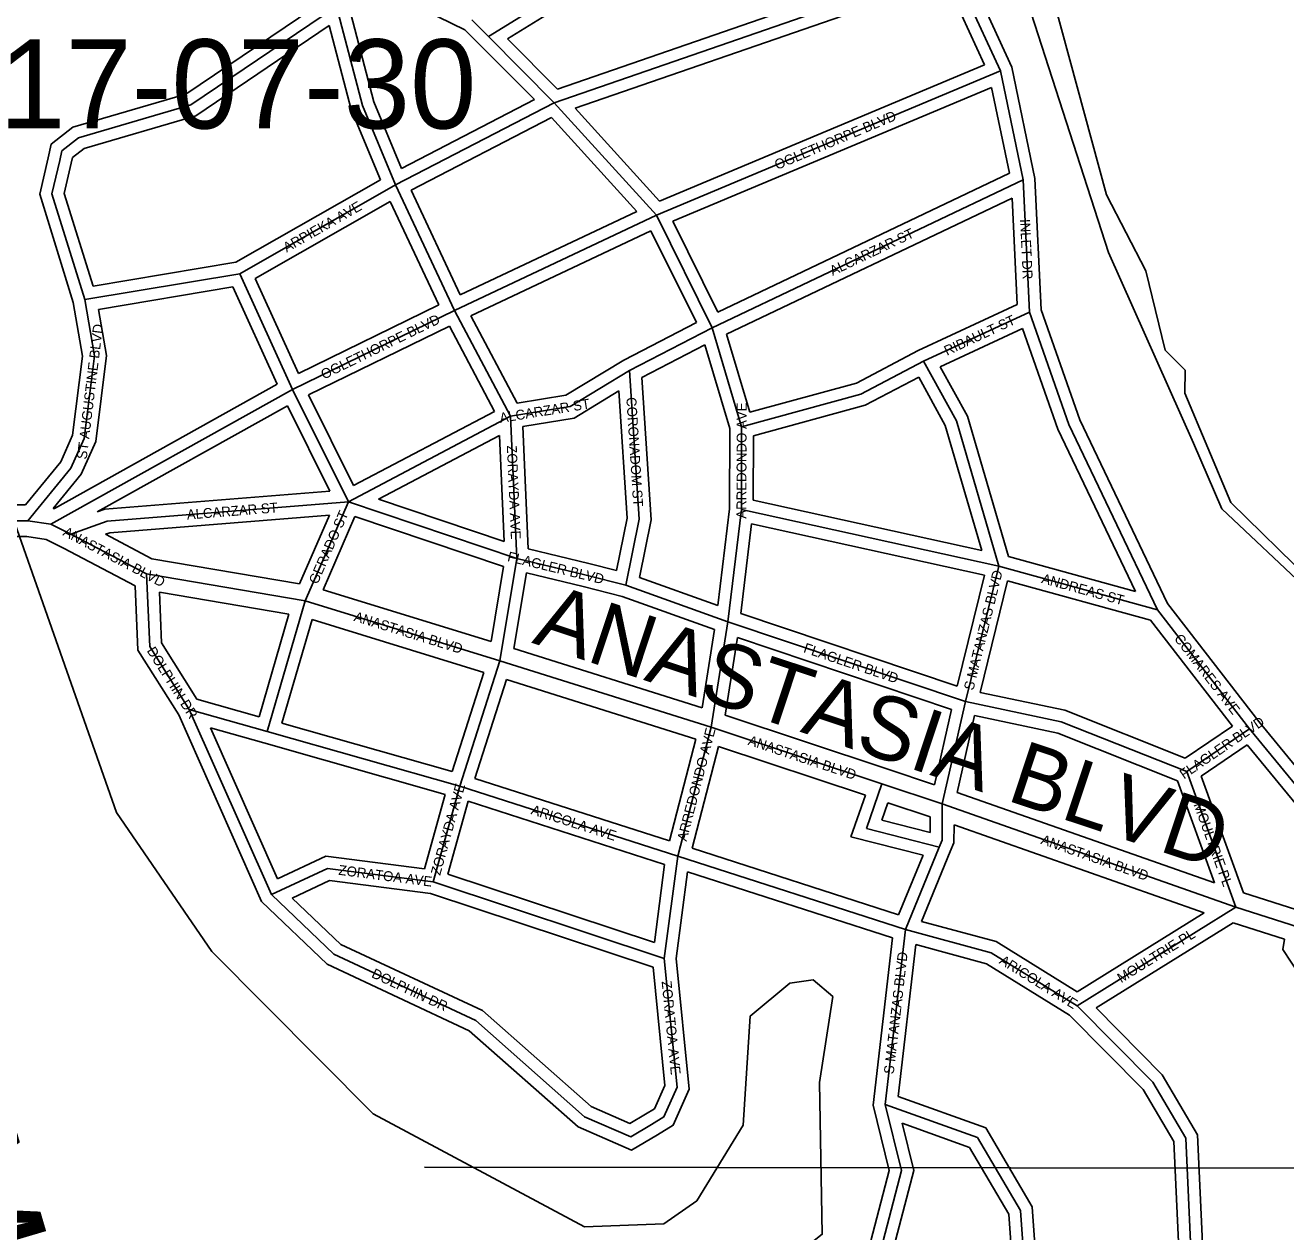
# Model space of a CAD drawing. Extents: x 418523 to 616617, y 1878279 to 2196743.
# Drawn here: x 559594 to 562775, y 2019372 to 2022418 of the extents above; entities that cross this region are included whole.
import ezdxf

# ---------------------------------------------------------------- set-up
doc = ezdxf.new("R2010")
doc.units = 0
for name, color, linetype in [('Level 1', 7, 'Continuous'), ('Level 2', 7, 'Continuous'), ('Level 22', 7, 'Continuous'), ('Level 23', 7, 'Continuous'), ('Level 28', 7, 'Continuous'), ('Level 31', 7, 'Continuous'), ('Level 32', 7, 'Continuous'), ('Level 34', 7, 'Continuous'), ('Level 41', 7, 'Continuous'), ('Level 5', 7, 'Continuous'), ('Level 8', 7, 'Continuous')]:
    doc.layers.add(name, color=color, linetype=linetype)

msp = doc.modelspace()

# ---------------------------------------------------------------- linework, layer by layer
at = {"layer": 'Level 1'}
msp.add_line((560601.032, 2019535.711), (562821.453, 2019532.989), dxfattribs=at)
at = {"layer": 'Level 22'}
for p, q in [((559565.211, 2021167.07), (559600.386, 2021166.976)), ((559658.673, 2021158.458), (559600.386, 2021166.976)), ((559708.677, 2021133.597), (559658.673, 2021158.458)), ((559900.133, 2021032.722), (559708.677, 2021133.597)), ((560300.195, 2020965.121), (559900.133, 2021032.722)), ((560791.625, 2020813.644), (560300.195, 2020965.121)), ((561324.529, 2020645.701), (560791.625, 2020813.644)), ((561755.46, 2020502.759), (561324.529, 2020645.701)), ((561907.759, 2020452.181), (561755.46, 2020502.759)), ((562648.96, 2020191.716), (561907.759, 2020452.181)), ((562807.282, 2020141.49), (562648.96, 2020191.716))]:
    msp.add_line(p, q, dxfattribs=at)
at = {"layer": 'Level 23'}
for p, q in [((559565.317, 2021207.07), (559594.329, 2021206.992)), ((559667.292, 2021197.624), (559664.475, 2021198.036)), ((559565.106, 2021127.069), (559597.427, 2021126.983)), ((559646.577, 2021119.8), (559597.427, 2021126.982)), ((559913.114, 2021071.096), (559795.86, 2021132.875)), ((559690.449, 2021097.988), (559646.577, 2021119.8)), ((559871.379, 2021002.659), (559690.448, 2021097.988)), ((560286.196, 2021008.054), (559913.114, 2021071.096)), ((560259.174, 2020931.485), (559932.106, 2020986.751)), ((560769.24, 2020862.402), (560345.145, 2020993.124)), ((560750.797, 2020784.37), (560317.7, 2020917.867)), ((561301.976, 2020694.75), (560827.088, 2020844.408)), ((561285.83, 2020615.956), (560808.082, 2020766.516)), ((561768.054, 2020540.725), (561359.77, 2020676.156)), ((561713.871, 2020474.41), (561343.012, 2020597.426)), ((561888.097, 2020500.86), (561768.067, 2020540.721)), ((562594.789, 2020253.151), (561945.205, 2020481.421)), ((561877.676, 2020420.021), (561770.823, 2020455.507)), ((562569.018, 2020177.407), (561937.624, 2020399.286)), ((562818.562, 2020179.876), (562667.832, 2020227.693)), ((562771.535, 2020110.865), (562641.863, 2020152.001))]:
    msp.add_line(p, q, dxfattribs=at)
at = {"layer": 'Level 31'}
for p, q in [((562054.481, 2022302.474), (561954.903, 2022519.473)), ((560928.699, 2022222.111), (561671.505, 2022478.747)), ((560762.453, 2022389.465), (560721.049, 2022431.031)), ((560928.699, 2022222.111), (560762.453, 2022389.465)), ((561186.54, 2021938.148), (562054.481, 2022302.474)), ((562112.082, 2022027.399), (562054.481, 2022302.474)), ((560527.931, 2022014.779), (560928.699, 2022222.111)), ((561186.54, 2021938.148), (560928.699, 2022222.111)), ((561327.455, 2021654.126), (562112.082, 2022027.399)), ((562127.705, 2021693.881), (562112.082, 2022027.399)), ((560135.671, 2021790.701), (560527.931, 2022014.779)), ((560677.31, 2021697.64), (560527.931, 2022014.779)), ((560677.31, 2021697.64), (561186.54, 2021938.148)), ((561327.455, 2021654.126), (561186.54, 2021938.148)), ((559743.824, 2021725.182), (560135.671, 2021790.701)), ((560268.318, 2021498.696), (560135.671, 2021790.701)), ((560268.318, 2021498.696), (560677.31, 2021697.64)), ((560818.265, 2021430.708), (560677.31, 2021697.64)), ((561860.563, 2021569.47), (562127.705, 2021693.881)), ((561118.662, 2021546.297), (561327.455, 2021654.126)), ((561401.595, 2021404.099), (561327.455, 2021654.126)), ((560968.535, 2021455.046), (561118.662, 2021546.297)), ((559658.673, 2021158.458), (560268.318, 2021498.696)), ((560409.227, 2021215.035), (560268.318, 2021498.696)), ((560818.265, 2021430.708), (560968.535, 2021455.046)), ((560409.227, 2021215.035), (560818.265, 2021430.708)), ((560834.127, 2021072.096), (560818.265, 2021430.708)), ((561401.055, 2021195.359), (561401.595, 2021404.099)), ((560300.195, 2020965.121), (560409.227, 2021215.035)), ((560834.127, 2021072.096), (560409.227, 2021215.035)), ((561367.048, 2020912.155), (561401.055, 2021195.359)), ((562050.954, 2021052.216), (561401.055, 2021195.359)), ((560791.625, 2020813.644), (560834.127, 2021072.096)), ((561008.944, 2021029.821), (560834.127, 2021072.096)), ((561966.732, 2020710.591), (562050.954, 2021052.216)), ((562450.912, 2020942.455), (562050.954, 2021052.216)), ((561109.017, 2021004.467), (561008.944, 2021029.821)), ((561367.048, 2020912.155), (561109.017, 2021004.467)), ((560300.195, 2020965.121), (560204.263, 2020635.168)), ((562683.381, 2020641.84), (562450.912, 2020942.455)), ((561324.529, 2020645.701), (561367.048, 2020912.155)), ((561966.732, 2020710.591), (561367.048, 2020912.155)), ((560690.66, 2020497.158), (560791.625, 2020813.644)), ((560214.91, 2020223.476), (560007.615, 2020690.961)), ((560204.263, 2020635.168), (560007.615, 2020690.961)), ((561907.759, 2020452.181), (561966.732, 2020710.591)), ((560690.66, 2020497.158), (560204.263, 2020635.168)), ((561240.343, 2020320.806), (561324.529, 2020645.701)), ((562524.973, 2020533.874), (562683.381, 2020641.84)), ((562648.96, 2020191.716), (562524.973, 2020533.874)), ((560623.481, 2020255.5), (560690.66, 2020497.158)), ((561240.343, 2020320.806), (560690.66, 2020497.158)), ((561755.46, 2020502.759), (561716.509, 2020390.488)), ((561716.509, 2020390.488), (561900.507, 2020343.465)), ((561815.043, 2020135.671), (561900.507, 2020343.465)), ((561206.399, 2020062.332), (561240.343, 2020320.806)), ((561815.043, 2020135.671), (561240.343, 2020320.806)), ((561206.399, 2020062.332), (560623.481, 2020255.5)), ((562248.074, 2019942.907), (562648.96, 2020191.716)), ((561763.835, 2019693.956), (561815.043, 2020135.671)), ((561997.18, 2019610.076), (561763.835, 2019693.956))]:
    msp.add_line(p, q, dxfattribs=at)
for points in [[(560762.453, 2022389.465), (561180.138, 2022646.576), (561321.935, 2022704.759)], [(559680.738, 2022076.645), (559686.187, 2022100.632), (559728.104, 2022133.616), (560011.617, 2022216.511), (560379.221, 2022465.381)], [(560527.931, 2022014.779), (560445.112, 2022215.01), (560379.221, 2022465.381)], [(559743.824, 2021725.182), (559661.185, 2021992.327), (559680.738, 2022076.645)], [(559600.386, 2021166.976), (559709.115, 2021300.153), (559742.586, 2021374.979), (559768.168, 2021583.29), (559743.824, 2021725.182)], [(562450.912, 2020942.455), (562227.115, 2021409.97), (562127.705, 2021693.881)], [(561109.017, 2021004.467), (561142.723, 2021171.3), (561118.662, 2021546.297)], [(561401.595, 2021404.099), (561702.22, 2021486.6), (561860.563, 2021569.47)], [(562050.954, 2021052.216), (561943.52, 2021419.064), (561860.563, 2021569.47)], [(559708.677, 2021133.597), (559800.663, 2021166.448), (560409.227, 2021215.035)], [(560007.615, 2020690.961), (559907.89, 2020849.416), (559900.133, 2021032.722)], [(562524.973, 2020533.874), (562208.395, 2020659.786), (561966.732, 2020710.591)], [(563190.289, 2019965.23), (562999.303, 2020257.371), (562683.381, 2020641.84)], [(561900.507, 2020343.465), (561907.523, 2020360.539), (561907.759, 2020452.181)], [(560214.91, 2020223.476), (560356.739, 2020289.654), (560623.481, 2020255.5)], [(561173.939, 2019643.116), (561121.886, 2019612.339), (561005.395, 2019662.827), (560730.951, 2019905.377), (560372.651, 2020072.871), (560214.91, 2020223.476)], [(562248.074, 2019942.907), (562031.655, 2020076.927), (561815.043, 2020135.671)], [(561206.399, 2020062.332), (561238.832, 2019737.135), (561205.362, 2019662.308), (561173.939, 2019643.116)], [(562522.294, 2019608.727), (562439.309, 2019750.404), (562248.074, 2019942.907)], [(561737.705, 2019268.903), (561805.238, 2019527.292), (561763.835, 2019693.956)], [(562368.22, 2018100.294), (562352.02, 2018333.441), (562153.115, 2018751.071), (562105.091, 2019426.149), (561997.18, 2019610.076)], [(562769.316, 2018424.016), (562636.49, 2018657.826), (562553.801, 2018916.601), (562522.294, 2019608.727)]]:
    msp.add_lwpolyline(points, dxfattribs=at)
at = {"layer": 'Level 32'}
for p, q in [((560703.345, 2022406.292), (560443.87, 2022533.227)), ((562083.155, 2022311.921), (561983.685, 2022528.685)), ((560936.707, 2022256.617), (561634.554, 2022497.72)), ((562014.285, 2022318.137), (561936.986, 2022486.589)), ((560981.485, 2022208.606), (561678.602, 2022449.457)), ((560741.199, 2022368.293), (560703.346, 2022406.292)), ((560878.603, 2022229.971), (560741.169, 2022368.321)), ((560936.707, 2022256.617), (560810.41, 2022383.756)), ((561194.49, 2021974.021), (562014.285, 2022318.137)), ((562141.939, 2022031.197), (562083.155, 2022311.921)), ((561227.62, 2021922.853), (562032.57, 2022260.739)), ((562077.882, 2022044.351), (562032.57, 2022260.739)), ((560543.167, 2022056.436), (560878.603, 2022229.971)), ((561194.491, 2021974.021), (560981.485, 2022208.606)), ((560567.389, 2022001.413), (560921.996, 2022184.865)), ((561137.097, 2021947.973), (560921.996, 2022184.864)), ((560125.441, 2021819.406), (560490.112, 2022027.724)), ((561341.215, 2021693.893), (562077.881, 2022044.35)), ((562157.469, 2021699.66), (562141.939, 2022031.197)), ((560691.655, 2021737.591), (560567.389, 2022001.413)), ((560174.295, 2021778.212), (560514.625, 2021972.625)), ((560637.545, 2021711.658), (560514.625, 2021972.625)), ((561363.513, 2021638.056), (562084.227, 2021980.923)), ((562096.796, 2021712.581), (562084.227, 2021980.923)), ((560691.655, 2021737.591), (561137.097, 2021947.974)), ((561341.215, 2021693.895), (561227.62, 2021922.853)), ((560718.487, 2021683.908), (561172.745, 2021898.453)), ((561287.461, 2021667.236), (561172.745, 2021898.453)), ((559764.737, 2021759.096), (560125.441, 2021819.407)), ((560282.893, 2021539.146), (560174.295, 2021778.212)), ((559778.488, 2021700.559), (560117.889, 2021757.309)), ((560229.581, 2021511.434), (560117.89, 2021757.31)), ((560282.894, 2021539.147), (560637.545, 2021711.658)), ((561847.269, 2021596.371), (562096.796, 2021712.58)), ((560834.734, 2021463.766), (560718.487, 2021683.908)), ((561103.97, 2021572.475), (561287.461, 2021667.236)), ((560308.645, 2021484.95), (560664.333, 2021657.966)), ((560777.719, 2021443.244), (560664.334, 2021657.966)), ((561422.001, 2021440.808), (561363.513, 2021638.056)), ((561902.346, 2021555.833), (562110.338, 2021652.697)), ((561149.858, 2021528.641), (561309.002, 2021610.831)), ((561371.584, 2021399.783), (561309.003, 2021610.831)), ((560957.957, 2021483.723), (561103.97, 2021572.475)), ((559667.291, 2021197.623), (560229.581, 2021511.433)), ((560422.422, 2021255.906), (560308.645, 2021484.95)), ((560834.734, 2021463.766), (560957.957, 2021483.723)), ((560979.114, 2021426.366), (561091.897, 2021494.919)), ((559775.58, 2021189.346), (560255.453, 2021457.16)), ((560362.627, 2021241.41), (560255.453, 2021457.158)), ((560422.422, 2021255.906), (560777.718, 2021443.244)), ((560849.416, 2021405.361), (560979.114, 2021426.366)), ((560485.146, 2021221.147), (560790.385, 2021382.091)), ((560802.223, 2021114.481), (560790.386, 2021382.091)), ((560863.102, 2021095.954), (560849.416, 2021405.361)), ((561371.06, 2021197.191), (561371.584, 2021399.782)), ((561431.118, 2021219.456), (561431.536, 2021381.206)), ((560802.223, 2021114.481), (560485.145, 2021221.147)), ((561341.745, 2020953.069), (561371.059, 2021197.191)), ((562007.921, 2021092.413), (561431.118, 2021219.456)), ((560286.195, 2021008.055), (560361.71, 2021181.144)), ((560345.145, 2020993.123), (560425.729, 2021177.83)), ((560800.385, 2021051.794), (560425.729, 2021177.831)), ((561399.746, 2020932.814), (561426.9, 2021158.946)), ((562014.465, 2021029.533), (561426.9, 2021158.946)), ((561016.311, 2021058.901), (560863.102, 2021095.954)), ((562395.478, 2020988.777), (562075.04, 2021076.716)), ((560769.24, 2020862.402), (560800.385, 2021051.794)), ((560827.088, 2020844.408), (560858.486, 2021035.34)), ((561001.576, 2021000.738), (560858.486, 2021035.34)), ((561085.85, 2021041.285), (561016.311, 2021058.901)), ((561100.261, 2020975.736), (561001.576, 2021000.738)), ((561341.745, 2020953.069), (561143.565, 2021023.969)), ((561945.405, 2020749.41), (562014.464, 2021029.533)), ((562003.295, 2020733.561), (562072.713, 2021015.135)), ((562433.31, 2020916.175), (562072.713, 2021015.135)), ((561333.5, 2020892.294), (561100.261, 2020975.736)), ((562706.843, 2020660.543), (562476.595, 2020958.283)), ((560259.174, 2020931.484), (560183.778, 2020672.165)), ((560317.7, 2020917.867), (560241.502, 2020655.786)), ((561945.405, 2020749.41), (561399.746, 2020932.814)), ((562640.162, 2020648.686), (562433.31, 2020916.175)), ((561301.976, 2020694.75), (561333.5, 2020892.294)), ((561359.77, 2020676.156), (561391.09, 2020872.425)), ((561931.445, 2020690.802), (561391.089, 2020872.425)), ((560670.908, 2020533.947), (560750.797, 2020784.37)), ((560728.346, 2020516.574), (560808.082, 2020766.517)), ((560183.778, 2020672.164), (560026.877, 2020716.681)), ((561888.097, 2020500.86), (561931.445, 2020690.801)), ((560189.895, 2020205.881), (559981.07, 2020676.816)), ((560670.908, 2020533.947), (560241.502, 2020655.786)), ((561945.205, 2020481.421), (561989.42, 2020675.165)), ((560229.94, 2020263.593), (560060.975, 2020644.636)), ((560196.075, 2020606.306), (560060.975, 2020644.636)), ((562521.249, 2020567.641), (562640.162, 2020648.686)), ((560653.764, 2020476.441), (560196.075, 2020606.306)), ((561219.269, 2020359.074), (561285.83, 2020615.956)), ((561276.485, 2020340.681), (561343.011, 2020597.426)), ((562561.114, 2020522.199), (562677.615, 2020601.603)), ((562667.832, 2020227.693), (562561.114, 2020522.199)), ((561219.268, 2020359.074), (560728.345, 2020516.573)), ((562594.789, 2020253.151), (562501.36, 2020510.978)), ((560601.533, 2020288.554), (560653.764, 2020476.441)), ((560660.039, 2020274.99), (560711.208, 2020459.059)), ((561207.34, 2020299.888), (560711.209, 2020459.06)), ((561713.871, 2020474.409), (561677.473, 2020369.499)), ((561770.822, 2020455.507), (561755.546, 2020411.476)), ((561755.547, 2020411.476), (561877.573, 2020380.29)), ((561877.573, 2020380.29), (561877.676, 2020420.021)), ((561677.472, 2020369.499), (561859.63, 2020322.946)), ((561797.846, 2020172.729), (561276.485, 2020340.681)), ((561855.73, 2020155.721), (561928.253, 2020332.053)), ((561181.38, 2020102.228), (561207.339, 2020299.888)), ((561797.847, 2020172.729), (561859.63, 2020322.946)), ((561181.38, 2020102.227), (560660.039, 2020274.99)), ((561236.596, 2020061.86), (561265.403, 2020281.215)), ((561782.408, 2020114.666), (561265.404, 2020281.215)), ((561178.479, 2020039.979), (560616.797, 2020226.109)), ((562248.057, 2019978.204), (562569.019, 2020177.407)), ((562295.931, 2019937.301), (562641.863, 2020152.001)), ((561733.408, 2019692.003), (561782.407, 2020114.666)), ((561796.377, 2019714.137), (561840.831, 2020097.592)), ((562017.557, 2019634.631), (561796.377, 2019714.137)), ((561976.805, 2019585.519), (561806.476, 2019646.746))]:
    msp.add_line(p, q, dxfattribs=at)
for points in [[(560810.411, 2022383.756), (561193.785, 2022619.749), (561329.097, 2022675.268)], [(559651.513, 2022083.422), (559659.285, 2022117.639), (559714.113, 2022160.781), (559998.689, 2022243.987), (560355.525, 2022485.566)], [(560543.167, 2022056.437), (560473.61, 2022224.605), (560410.99, 2022462.544)], [(559709.993, 2022069.999), (559713.09, 2022083.626), (559742.095, 2022106.449), (560024.545, 2022189.034), (560360.985, 2022416.803)], [(560490.112, 2022027.724), (560416.615, 2022205.415), (560360.985, 2022416.804)], [(559714.586, 2021718.182), (559630.129, 2021991.206), (559651.513, 2022083.422)], [(559764.737, 2021759.096), (559692.242, 2021993.447), (559709.963, 2022069.868)], [(559594.328, 2021206.992), (559683.355, 2021316.041), (559713.359, 2021383.112), (559737.853, 2021582.567), (559714.586, 2021718.182)], [(559664.475, 2021198.036), (559734.874, 2021284.266), (559771.814, 2021366.846), (559798.483, 2021584.013), (559778.488, 2021700.559)], [(562476.595, 2020958.283), (562254.885, 2021421.438), (562157.469, 2021699.66)], [(562395.478, 2020988.777), (562199.343, 2021398.502), (562110.339, 2021652.697)], [(561422.001, 2021440.809), (561691.169, 2021514.677), (561847.268, 2021596.371)], [(562075.041, 2021076.716), (561971.383, 2021430.662), (561902.346, 2021555.833)], [(561143.565, 2021023.97), (561172.916, 2021169.255), (561149.858, 2021528.641)], [(561431.536, 2021381.206), (561713.272, 2021458.522), (561848.47, 2021529.277)], [(562007.921, 2021092.413), (561915.655, 2021407.465), (561848.47, 2021529.277)], [(561085.85, 2021041.284), (561112.53, 2021173.346), (561091.896, 2021494.919)], [(559775.58, 2021189.346), (559794.315, 2021196.037), (560362.628, 2021241.409)], [(559795.86, 2021132.876), (559807.01, 2021136.859), (560361.71, 2021181.144)], [(559981.07, 2020676.816), (559878.254, 2020840.183), (559871.379, 2021002.659)], [(560026.877, 2020716.681), (559937.528, 2020858.65), (559932.106, 2020986.751)], [(562521.249, 2020567.641), (562217.089, 2020688.614), (562003.295, 2020733.561)], [(562501.361, 2020510.978), (562199.703, 2020630.956), (561989.42, 2020675.165)], [(563200.542, 2020004.372), (563023.52, 2020275.156), (562706.843, 2020660.542)], [(563087.504, 2020067.629), (562975.086, 2020239.587), (562677.615, 2020601.602)], [(561928.256, 2020332.063), (561937.509, 2020354.578), (561937.624, 2020399.286)], [(560229.94, 2020263.593), (560351.929, 2020320.516), (560601.533, 2020288.555)], [(560267.385, 2020214.853), (560361.549, 2020258.792), (560616.797, 2020226.109)], [(561189.208, 2019617.291), (561123.99, 2019578.73), (560989.096, 2019637.194), (560714.326, 2019880.032), (560355.491, 2020047.776), (560189.895, 2020205.881)], [(561158.67, 2019668.939), (561119.783, 2019645.948), (561021.695, 2019688.461), (560747.576, 2019930.722), (560389.811, 2020097.966), (560267.385, 2020214.853)], [(562248.056, 2019978.205), (562043.729, 2020104.737), (561855.73, 2020155.721)], [(562858.978, 2019612.795), (562851.433, 2019890.733), (562851.601, 2019957.012), (562767.003, 2020084.696), (562771.535, 2020110.865)], [(562229.279, 2019919.26), (562019.58, 2020049.117), (561840.831, 2020097.593)], [(561236.596, 2020061.861), (561269.477, 2019732.171), (561228.946, 2019641.559), (561189.208, 2019617.291)], [(561178.479, 2020039.978), (561208.187, 2019742.1), (561181.778, 2019683.057), (561158.67, 2019668.939)], [(562492.662, 2019599.958), (562415.345, 2019731.959), (562229.279, 2019919.258)], [(562551.926, 2019617.495), (562463.273, 2019768.849), (562295.932, 2019937.301)], [(561711.76, 2019288.274), (561774.279, 2019527.48), (561733.408, 2019692.004)], [(561767.479, 2019264.179), (561836.197, 2019527.104), (561806.476, 2019646.746)], [(562398.148, 2018102.373), (562381.554, 2018341.201), (562182.638, 2018758.853), (562134.518, 2019435.278), (562017.557, 2019634.63)], [(562739.755, 2018415.319), (562608.863, 2018645.721), (562524.012, 2018911.26), (562492.662, 2019599.958)], [(562784.178, 2018458.59), (562664.117, 2018669.931), (562583.59, 2018921.941), (562551.926, 2019617.495)], [(562334.205, 2018157.021), (562322.485, 2018325.681), (562123.592, 2018743.289), (562075.664, 2019417.021), (561976.805, 2019585.52)]]:
    msp.add_lwpolyline(points, dxfattribs=at)
at = {"layer": 'Level 5'}
for points in [[(560134.827, 2023630.755), (559892.345, 2023406.456), (559733.335, 2023215.24), (559599.106, 2022957.242), (559531.599, 2022699.046), (559506.529, 2022682.436), (559470.99, 2021998.949), (559512.025, 2021798.745), (559551.776, 2021206.732), (559824.366, 2020430.577), (560065.008, 2020079.662), (560472.155, 2019669.868), (561004.763, 2019384.707)], [(567869.335, 2015369.358), (567670.405, 2015720.134), (567221.577, 2016130.058), (566657.518, 2017007.201), (566317.719, 2017625.201), (565852.479, 2018118.556), (565512.65, 2018728.216), (564964.605, 2019396.895), (564656.904, 2019622.986), (564390.466, 2019723.876), (564174.477, 2019966.349), (563641.73, 2020209.808), (563508.675, 2020301.958), (563300.956, 2020519.361), (563234.623, 2020627.962), (562636.299, 2021213.439), (562520.47, 2021488.924), (562520.67, 2021547.285), (562470.808, 2021597.466), (562421.413, 2021797.67), (562321.997, 2021989.733), (562116.039, 2022749.028)], [(561004.763, 2019384.707), (561204.867, 2019392.38), (561288.428, 2019450.482), (561405.757, 2019641.858), (561423.313, 2019916.885), (561523.614, 2019999.928), (561581.995, 2020008.069), (561631.887, 2019966.218), (561597.82, 2019749.603), (561604.947, 2019366.104), (561479.575, 2019266.461), (561245.703, 2019133.825), (561212.133, 2019058.932)]]:
    msp.add_lwpolyline(points, dxfattribs=at)
at = {"layer": 'Level 8'}
msp.add_lwpolyline([(562035.047, 2022750.826), (562327.07, 2021843.81), (562542.084, 2021362.801), (562613.088, 2021196.798), (562831.097, 2020991.796), (563060.106, 2020767.794), (563234.114, 2020592.791), (563317.118, 2020450.79), (563506.125, 2020268.787), (563632.13, 2020203.787), (563783.135, 2020125.787), (563943.14, 2020042.787), (564144.146, 2019949.788), (564352.155, 2019699.785), (564498.16, 2019653.786), (564607.163, 2019613.786), (564656.165, 2019595.786), (564885.173, 2019410.785), (564950.175, 2019363.784), (565146.185, 2019116.781), (565479.2, 2018721.776), (565669.21, 2018393.771), (565764.215, 2018229.768), (565850.22, 2018090.766)], dxfattribs=at)

# ---------------------------------------------------------------- texts
at = {"layer": 'Level 2'}
msp.add_text('17-07-30', height=225, dxfattribs=at).set_placement((559527.855, 2022157.152))
at = {"layer": 'Level 28'}
msp.add_text('ANASTASIA BLVD', height=160, rotation=341.648253, dxfattribs=at).set_placement((560870.193, 2020859.32))
at = {"layer": 'Level 34'}
for s, height, rotation, p in [('OGLETHORPE BLVD', 25, 22.769989, (561491.177, 2022052.469)), ('ARPIEKA AVE', 25, 29.736414, (560253.494, 2021843.613)), ('INLET DR', 25, 272.680836, (562104.224, 2021928.013)), ('ALCARZAR ST', 25, 25.441175, (561631.279, 2021784.826)), ('OGLETHORPE BLVD', 24.99916, 25.938675, (560347.432, 2021523.282)), ('RIBAULT ST', 25, 24.971339, (561919.752, 2021583.246)), ('ST AUGUSTINE BLVD', 25, 82.997597, (559748.546, 2021320.992)), ('CORONADOM ST', 25, 273.670411, (561110.505, 2021478.225)), ('ALCARZAR ST', 25, 9.19895, (560792.798, 2021413.922)), ('ARREDONDO AVE', 25, 89.850847, (561413.491, 2021172.14)), ('ZORAYDA AVE', 25, 272.531711, (560809.012, 2021357.046)), ('ALCARZAR ST', 25, 4.564025, (560002.331, 2021170.011)), ('GERADO ST', 25, 66.428503, (560331.216, 2021004.971)), ('ANASTASIA BLVD', 25, 332.215281, (559686.561, 2021131.123)), ('FLAGLER BLVD', 25, 346.404317, (560808.846, 2021065.352)), ('S MATANZAS BLVD', 25, 76.149933, (561986.26, 2020737.591)), ('ANDREAS ST', 25, 344.653247, (562156.505, 2021010.289)), ('ANASTASIA BLVD', 25, 342.868, (560421.231, 2020914.736)), ('COMARES AVE', 25, 307.714267, (562491.654, 2020869.339)), ('DOLPHIN DR', 25, 302.183375, (559899.612, 2020839.103)), ('FLAGLER BLVD', 25, 341.420986, (561555.878, 2020835.501)), ('FLAGLER BLVD', 25, 34.276242, (562517.912, 2020513.936)), ('ARREDONDO AVE', 25, 75.472183, (561262.536, 2020356.638)), ('ANASTASIA BLVD', 25, 341.648253, (561415.882, 2020602.231)), ('ZORAYDA AVE', 25, 74.463589, (560640.641, 2020270.567)), ('ARICOLA AVE', 25, 342.211739, (560868.113, 2020427.102)), ('MOULTRIE PL', 25, 289.917675, (562541.737, 2020450.926)), ('ANASTASIA BLVD', 25, 340.63725, (562154.761, 2020352.135)), ('ZORATOA AVE', 25, 352.702667, (560383.084, 2020273.681)), ('MOULTRIE PL', 25, 31.800681, (562359.437, 2019999.654)), ('S MATANZAS BLVD', 25, 83.386203, (561785.15, 2019769.3)), ('ARICOLA AVE', 25, 328.230872, (562049.737, 2020051.028)), ('DOLPHIN DR', 25, 334.944664, (560465.618, 2020015.614)), ('ZORATOA AVE', 25, 275.694422, (561199.63, 2020004.269))]:
    msp.add_text(s, height=height, rotation=rotation, dxfattribs=at).set_placement(p)
at = {"layer": 'Level 41'}
msp.add_text('Matanzas River', height=320, rotation=286.452267, dxfattribs=at).set_placement((559248.603, 2019591.812))

doc.saveas('drawing.dxf')
